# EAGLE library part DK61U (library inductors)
FILTER
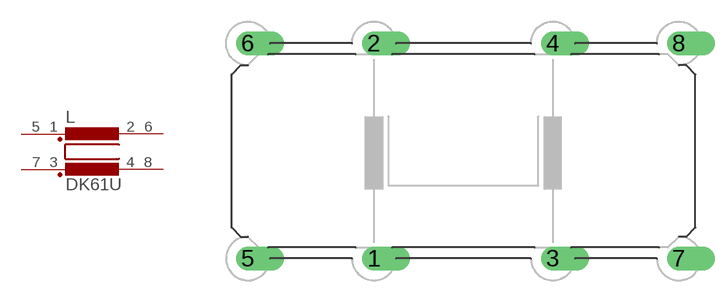
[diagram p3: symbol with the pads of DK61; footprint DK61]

Designator prefix L

## DK61U  [DK61]
1  1  pas
2  2  pas
3  3  pas
4  4  pas
5  5  pas
6  6  pas
7  7  pas
8  8  pas

## Footprint DK61 (pad centres in mm)
FILTER manufacturer Vogt
drill 1.118 offset: 1 -6.223,-7.493; 2 -6.223,7.493; 3 6.223,-7.493; 4 6.223,7.493; 5 -14.986,-7.493; 6 -14.986,7.493; 7 14.986,-7.493; 8 14.986,7.493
